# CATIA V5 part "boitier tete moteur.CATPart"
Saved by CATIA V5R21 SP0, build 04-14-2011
Part number: boitier tete moteur
Material "Aluminium": density 2710 kg/m3, Young's modulus 7e+10 Pa, Poisson ratio 0.346, thermal expansion 2.36e-05 1/K
Bounding box of the stored display mesh (mm): x -15.717 to 15.717, y 0 to 14, z -15.717 to 15.717
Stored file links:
  C:\Users\Olivier\Desktop\redaction CATIA (local)\CATIA\DONNEES\Exercice assemblage 3 (Pompe de ventilation)\Assemblage ensemble bloc moteur (Product inclus)\boitier tete moteur.CATPart
  C:\Program Files\Dassault Systemes\B21\win_b64\startup\materials\French\Catalog.CATMaterial
  C:\Users\Olivier\Desktop\redaction CATIA (local)\CATIA\DONNEES\Exercice assemblage 3 (Pompe de ventilation)\Assemblage ensemble bloc moteur (Product inclus)\CATIA_EnvironmentMap_DSBlack_512x512.jpg
  C:\Users\Olivier\Desktop\redaction CATIA (local)\pompe à moteur de ventilation refait\Pompe_a_moteur_de_ventilation.CATProduct
  C:\Users\Olivier\Desktop\redaction CATIA (local)\pompe à moteur de ventilation refait\Ecrou a collerette M5.CATPart
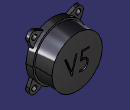
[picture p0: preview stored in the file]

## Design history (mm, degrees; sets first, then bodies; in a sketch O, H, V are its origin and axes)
Body1 (main body), material "Aluminium"
  Sketch1 on zx-plane, origin (0, 0, 0), H (-1, 0, 0), V (0, 0, 1)
    circle A1 centre (0, 0) radius 15.5
    circle A2 centre (0, 0) radius 14.5
    radius A2 = 14.5
  MultiPad1: profile Sketch1, domains (length 14; length 4)
  Sketch2 on face of MultiPad1, origin (0, 0, 0), H (1, 0, 0), V (0, 0, 1)
    circle A1 centre (0, 0) radius 11.5
  Pocket1: profile Sketch2, direction (0, 1, 0), length 12
  Sketch3 on face of MultiPad1, origin (0, 0, 0), H (1, 0, 0), V (0, 0, 1)
    projected circle E1 centre (0, 0) radius 15.5 from edge [face of MultiPad1 | face of MultiPad1 from Sketch1.A1]
    projected arc E2 centre (0, 0) radius 15.5 from (-7.465, 13.5839) to (-13.5839, 7.465) ccw from edge [face of MultiPad1 | face of MultiPad1 from Sketch1.A1]
    projected arc E3 centre (0, 0) radius 15.5 from (-13.5839, -7.465) to (-7.465, -13.5839) ccw from edge [face of MultiPad1 | face of MultiPad1 from Sketch1.A1]
    projected arc E4 centre (0, 0) radius 15.5 from (7.465, -13.5839) to (13.5839, -7.465) ccw from edge [face of MultiPad1 | face of MultiPad1 from Sketch1.A1]
    projected arc E5 centre (0, 0) radius 15.5 from (13.5839, 7.465) to (7.465, 13.5839) ccw from edge [face of MultiPad1 | face of MultiPad1 from Sketch1.A1]
    circle A1 centre (12.7279, 12.7279) radius 1.5
    point P1 (12.7279, 12.7279)
    arc A2 centre (12.7279, 12.7279) radius 3 from (15.4468, 11.4601) to (11.4601, 15.4468) ccw
    line L1 (15.4468, 11.4601) -> (13.5839, 7.465)
    point P2 (15.4468, 11.4601)
    point P3 (11.4601, 15.4468)
    line L2 (11.4601, 15.4468) -> (7.465, 13.5839)
    point P4 (7.465, 13.5839)
    point P5 (13.5839, 7.465)
    point P7 (-15.4468, 11.4601)
    point P8 (-11.4601, 15.4468)
    point P9 (-7.465, 13.5839)
    point P10 (-13.5839, 7.465)
    circle A3 centre (-12.7279, 12.7279) radius 1.5
    arc A4 centre (-12.7279, 12.7279) radius 3 from (-15.4468, 11.4601) to (-11.4601, 15.4468) cw
    line L3 (-15.4468, 11.4601) -> (-13.5839, 7.465)
    line L4 (-11.4601, 15.4468) -> (-7.465, 13.5839)
    point P12 (15.4468, -11.4601)
    point P13 (11.4601, -15.4468)
    point P14 (7.465, -13.5839)
    point P15 (13.5839, -7.465)
    point P17 (-15.4468, -11.4601)
    point P18 (-11.4601, -15.4468)
    point P19 (-7.465, -13.5839)
    point P20 (-13.5839, -7.465)
    circle A5 centre (12.7279, -12.7279) radius 1.5
    arc A6 centre (12.7279, -12.7279) radius 3 from (15.4468, -11.4601) to (11.4601, -15.4468) cw
    line L5 (15.4468, -11.4601) -> (13.5839, -7.465)
    line L6 (11.4601, -15.4468) -> (7.465, -13.5839)
    circle A7 centre (-12.7279, -12.7279) radius 1.5
    arc A8 centre (-12.7279, -12.7279) radius 3 from (-15.4468, -11.4601) to (-11.4601, -15.4468) ccw
    line L7 (-15.4468, -11.4601) -> (-13.5839, -7.465)
    line L8 (-11.4601, -15.4468) -> (-7.465, -13.5839)
    distance P1 O = 18
    radius A2 = 3
    tangency: A2 L1
    coincidence: E1 P4, E1 P5
    symmetry: P2 P7 V, P3 P8 V, P4 P9 V, P5 P10 V, A1 A3 V, A2 A4 V, L1 L3 V, L2 L4 V, P2 P12 H, P3 P13 H, P4 P14 H, P5 P15 H, P7 P17 H, P8 P18 H, P9 P19 H, P10 P20 H, A1 A5 H, A2 A6 H, L1 L5 H, L2 L6 H, A3 A7 H, A4 A8 H, L3 L7 H, L4 L8 H
  Pad1: profile Sketch3, direction (0, 1, 0), length 2
  Sketch4 on face of MultiPad1, origin (0, 14, 0), H (-1, 0, 0), V (0, 0, 1)
    line L1 (-7.2074, 4.3533) -> (-3.0577, -5.6747)
    point P2 (-3.0577, -5.6747)
    point P3 (-3.0577, -5.6747)
    point P4 (0.0056, 4.3533)
    line L2 (0.0056, 4.3533) -> (-3.0577, -5.6747)
    line L3 (-7.2074, 4.3533) -> (-6.1898, 4.3533)
    line L4 (-6.1898, 4.3533) -> (-3.0677, -3.1914)
    line L5 (-3.0677, -3.1914) -> (-0.7629, 4.3533)
    point P7 (-0.7629, 4.3533)
    line L6 (-0.7629, 4.3533) -> (0.0056, 4.3533)
    point P8 (0.0056, 4.3533)
    point P9 (2.7205, 4.3533)
    line L7 (2.7205, 4.3533) -> (2.0273, -0.6137)
    line L8 (2.7205, 4.3533) -> (7.0034, 4.3533)
    line L9 (7.0034, 4.3533) -> (6.8938, 3.5681)
    line L10 (6.8938, 3.5681) -> (3.3501, 3.5681)
    line L11 (3.3501, 3.5681) -> (2.8903, 0.2738)
    point P14 (2.8903, 0.2738)
    spline S1 through (2.8903, 0.2738) (6.1305, -1.2523) (5.8312, -4.3043) (1.3117, -5.7405)
    offsetcurve C1
    construction line L12 (2.8903, 0.2738) -> (2.9402, -0.6249)
    point P17 (2.8903, 0.2738)
    construction line L13 through (2.8903, 0.2738) direction (-0.9985, -0.0554)
    construction line L14 (1.3117, -5.7405) -> (1.5746, -4.8798)
    point P18 (1.3117, -5.7405)
    construction line L15 through (1.1611, -5.6945) direction (-0.9564, 0.2922)
    line L16 (2.9402, -0.6249) -> (2.0273, -0.6137)
    line L17 (1.5746, -4.8798) -> (1.3117, -5.7405)
    point P19 (1.3117, -5.7405)
    point P20 (2.8903, 0.2738)
    point P21 (1.3117, -5.7405)
    horizontal: L3 H, L6 H, L8 H, L10 H
    parallelism: L4 L1, L5 L2, L9 L7, L11 L7, L17 L2
    coincidence: P7 L3, P8 L2, P9 L6, P20 P14, P21 L7, P20 P17, P21 P18, P4 P8, P19 P21, P2 P3
    tangency: L13 S1, L15 S1
    perpendicularity: L12 L13, L14 L15
  Pocket2: profile Sketch4, direction (0, -1, 0), length 1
